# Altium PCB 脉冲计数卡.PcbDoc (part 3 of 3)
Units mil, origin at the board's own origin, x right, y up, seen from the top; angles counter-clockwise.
Board outline 5137.66 x 6771.53 mil, 4 copper layers (Top Layer, GND, VCC, Bottom Layer); 160 components, 225 nets, 1035 pads, 287 vias.
Unrouted connection lines stored in the file: 61.
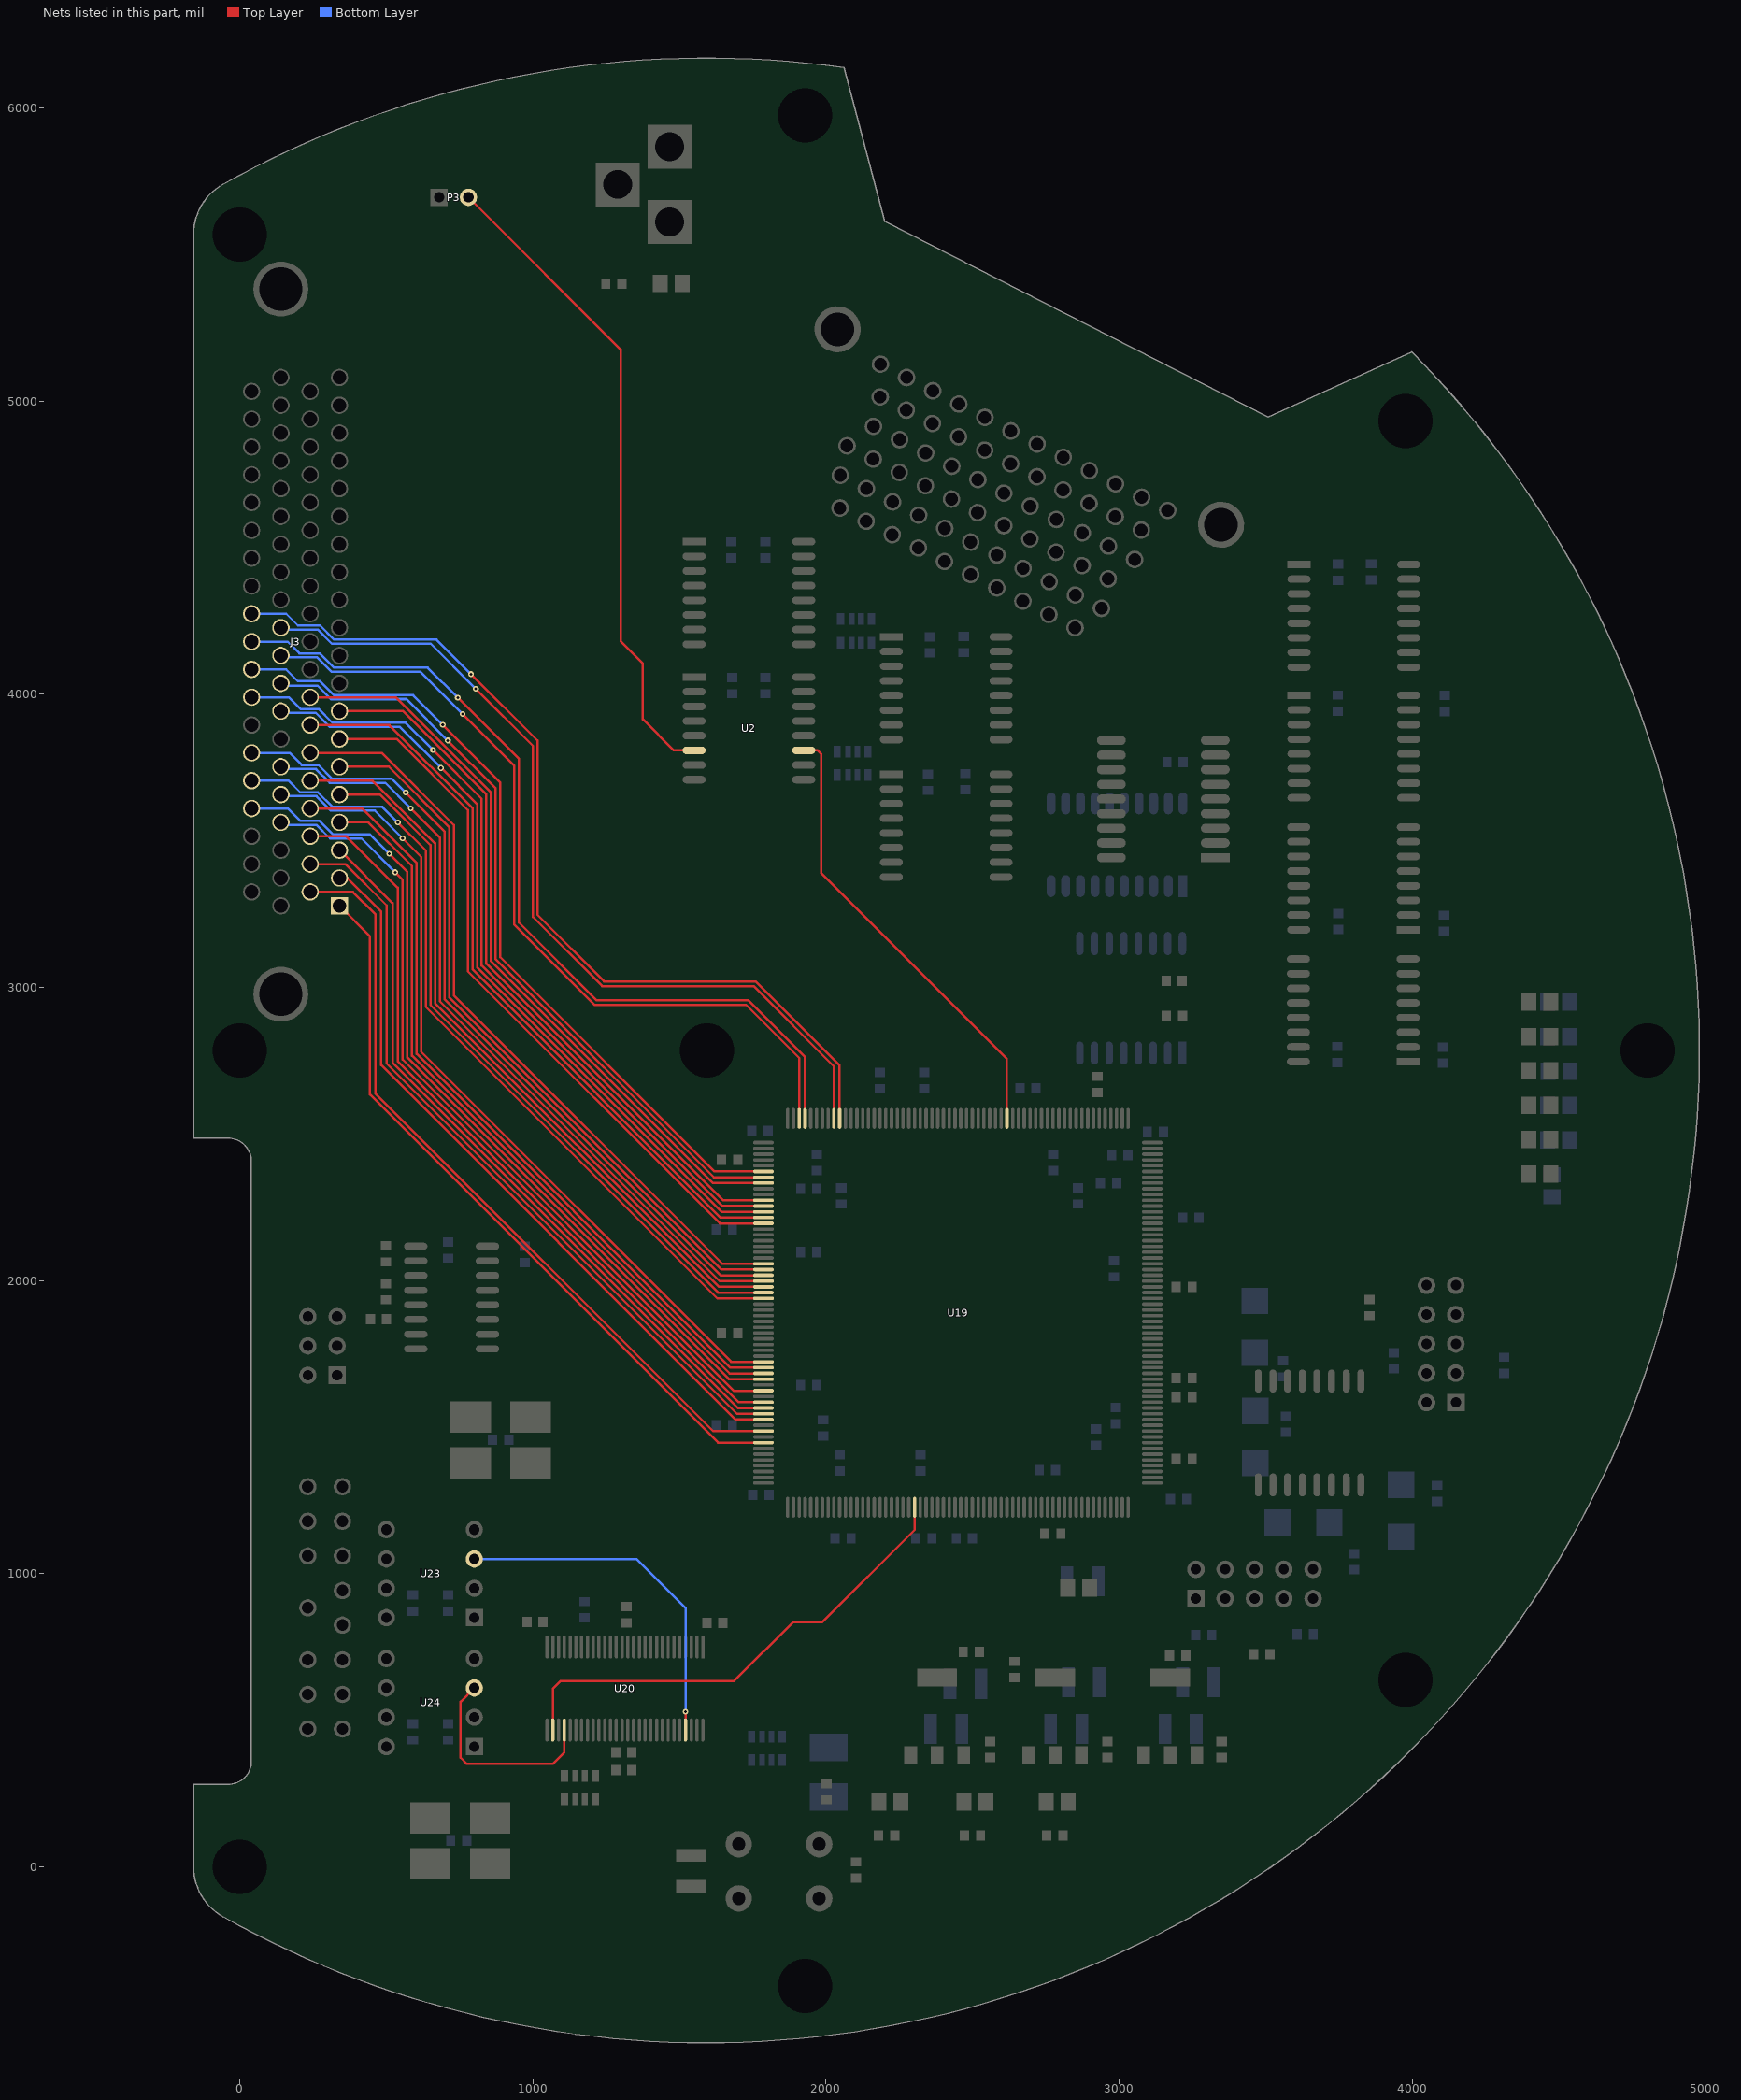
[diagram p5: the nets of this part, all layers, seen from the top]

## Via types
v1: diameter 20, hole 10, Top Layer to Bottom Layer, 184 vias
v2: diameter 40, hole 20, Top Layer to Bottom Layer, 82 vias
v3: diameter 15, hole 8, Top Layer to Bottom Layer, 11 vias
v4: diameter 60, hole 30, Top Layer to Bottom Layer, 8 vias
v5: diameter 30, hole 15, Top Layer to Bottom Layer, 2 vias

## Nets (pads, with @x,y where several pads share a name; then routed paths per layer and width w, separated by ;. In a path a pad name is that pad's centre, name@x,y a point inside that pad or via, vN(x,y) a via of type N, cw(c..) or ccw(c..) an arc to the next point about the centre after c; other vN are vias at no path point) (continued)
TA2: J3.67 U19.144 | length 2820.5
  Top Layer w8: v1(566,3665) 698.32,3532.68 698.32,2959.89 1640.25,2017.95 U19.144@1786.61,2017.95
  Bottom Layer w8: J3.67@40,3800.47 169.53,3800.47 211,3759 268,3759 315,3712 519,3712 v1(566,3665)
TA3: J3.12 U19.142 | length 2609.2
  Top Layer w8: J3.12@240,3800.47 483.91,3800.47 730.06,3554.32 730.06,2973.04 1645.78,2057.32 U19.142@1786.61,2057.32
TA4: J3.13 U19.135 | length 2453.4
  Top Layer w8: J3.13@340,3847.91 535.09,3847.91 777.69,3605.31 777.69,3055.31 1637.88,2195.12 U19.135@1786.61,2195.12
TA5: J3.68 U19.145 | length 2700.5
  Top Layer w8: v1(583,3611) 682.44,3511.56 682.44,2953.31 1637.49,1998.27 U19.145@1786.61,1998.27
  Bottom Layer w8: J3.68@140,3753.03 148.03,3745 260,3745 307,3698 496,3698 v1(583,3611)
TA6: J3.9 U19.147 | length 2469.8
  Top Layer w8: J3.9@340,3658.15 477.85,3658.15 650.69,3485.31 650.69,2940.16 1631.96,1958.9 U19.147@1786.61,1958.9
TA7: J3.11 U19.143 | length 2497.7
  Top Layer w8: J3.11@340,3753.03 508.9,3753.03 714.19,3547.75 714.19,2966.46 1643.01,2037.64 U19.143@1786.61,2037.64
TA8: J3.15 U19.131 | length 2476
  Top Layer w8: J3.15@340,3942.8 557.14,3942.8 841.18,3658.75 841.18,3081.62 1648.94,2273.86 U19.131@1786.61,2273.86
TA9: J3.69 U19.148 | length 2790.8
  Top Layer w8: v1(539,3563) 634.82,3467.18 634.82,2933.59 1629.19,1939.21 U19.148@1786.61,1939.21
  Bottom Layer w8: J3.69@40,3705.59 166.41,3705.59 206,3666 266.38,3666 316.38,3616 486,3616 v1(539,3563)
TA10: J3.72 U19.164 | length 2809.2
  Top Layer w8: v1(530,3393) 555.45,3367.55 555.45,2753.9 1685.1,1624.25 U19.164@1786.61,1624.25
  Bottom Layer w8: J3.72@140,3563.27 148.27,3555 261,3555 308,3508 415,3508 v1(530,3393)
TA11: J3.16 U19.128 | length 2570.2
  Top Layer w8: J3.16@240,3990.24 532.15,3990.24 857.06,3665.33 857.06,3089.94 1614.09,2332.91 U19.128@1786.61,2332.91
TA12: J3.70 U19.159 | length 2837.7
  Top Layer w8: v1(555,3509) 618.95,3445.05 618.95,2780.4 1676.67,1722.68 U19.159@1786.61,1722.68
  Bottom Layer w8: J3.70@140,3658.15 145.15,3653 261,3653 311,3603 461,3603 v1(555,3509)
TA13: J3.71 U19.162 | length 2924.5
  Top Layer w8: v1(510,3456) 571.32,3394.68 571.32,2760.68 1668.38,1663.62 U19.162@1786.61,1663.62
  Bottom Layer w8: J3.71@40,3610.71 164,3610.71 205.71,3569 271,3569 317,3523 443,3523 v1(510,3456)
TA14: J3.14 U19.134 | length 2564.9
  Top Layer w8: J3.14@240,3895.35 510.09,3895.35 793.56,3611.89 793.56,3061.89 1640.65,2214.8 U19.134@1786.61,2214.8
TA15: J3.10 U19.146 | length 2581.3
  Top Layer w8: J3.10@240,3705.59 452.86,3705.59 666.57,3491.88 666.57,2946.74 1634.72,1978.58 U19.146@1786.61,1978.58
TD0: J3.63 U19.132 | length 2798.8
  Top Layer w8: v1(659,3810) 825.31,3643.69 825.31,3075.04 1646.17,2254.17 U19.132@1786.61,2254.17
  Bottom Layer w8: J3.63@40,3990.24 166.76,3990.24 207,3950 269,3950 316,3903 566,3903 v1(659,3810)
TD1: J3.64 U19.133 | length 2680.6
  Top Layer w8: v1(686,3749) 809.43,3625.57 809.43,3068.47 1643.41,2234.49 U19.133@1786.61,2234.49
  Bottom Layer w8: J3.64@140,3942.8 145.8,3937 259,3937 307,3889 546,3889 v1(686,3749)
TD2: J3.6 U19.166 | length 2693.3
  Top Layer w8: J3.6@240,3515.83 363.17,3515.83 539,3340 539,2747.9 1702.02,1584.88 U19.166@1786.61,1584.88
TD3: J3.62 U19.127 | length 2685.8
  Top Layer w8: v1(709.5,3842.5) 872.93,3679.07 872.93,3096.52 1616.85,2352.6 U19.127@1786.61,2352.6
  Bottom Layer w8: J3.62@140,4037.68 147.68,4030 265,4030 311,3984 568,3984 v1(709.5,3842.5)
TD4: J3.7 U19.161 | length 2604.2
  Top Layer w8: J3.7@340,3563.27 438,3563.27 587.2,3414.07 587.2,2767.25 1671.14,1683.31 U19.161@1786.61,1683.31
TD5: J3.5 U19.167 | length 2553.6
  Top Layer w8: J3.5@340,3468.39 521,3287.39 521,2743.45 1699.25,1565.2 U19.167@1786.61,1565.2
TD6: J3.8 U19.160 | length 2718.1
  Top Layer w8: J3.8@240,3610.71 417,3610.71 603.07,3424.64 603.07,2773.83 1673.91,1702.99 U19.160@1786.61,1702.99
TD7: J3.4 U19.168 | length 2639.2
  Top Layer w8: J3.4@240,3420.94 360.06,3420.94 501,3280 501,2741 1696.49,1545.51 U19.168@1786.61,1545.51
TD8: J3.61 U19.126 | length 2805.3
  Top Layer w8: v1(692,3896) 888.8,3699.2 888.8,3103.1 1619.61,2372.28 U19.126@1786.61,2372.28
  Bottom Layer w8: J3.61@40,4085.12 157.88,4085.12 198,4045 274,4045 322,3997 591,3997 v1(692,3896)
TD9: J3.2 U19.171 | length 2668.4
  Top Layer w8: J3.2@240,3326.06 385.94,3326.06 462,3250 462,2639 1614.54,1486.46 U19.171@1786.61,1486.46 U19.171@1784.71,1486.46
TD10: J3.57 U19.111 | length 3173.6
  Top Layer w8: v1(789,4069) 1015.8,3842.2 1015.8,3247.45 1242.88,3020.37 1759.88,3020.37 2046.46,2733.79 U19.111@2046.46,2553.39
  Bottom Layer w8: J3.57@40,4274.88 158.12,4274.88 198,4235 274,4235 322,4187 671,4187 v1(789,4069)
TD11: J3.58 U19.112 | length 3025.9
  Top Layer w8: v1(805,4019) 999.92,3824.08 999.92,3240.88 1236.3,3004.5 1753.3,3004.5 2026.77,2731.03 U19.112@2026.77,2553.39
  Bottom Layer w8: J3.58@140,4227.44 147.44,4220 267,4220 314,4173 651,4173 v1(805,4019)
TD12: J3.3 U19.169 | length 2518.3
  Top Layer w8: J3.3@340,3373.5 366.5,3373.5 482,3258 482,2735 1691.17,1525.83 U19.169@1786.61,1525.83
TD13: J3.60 U19.118 | length 2860.9
  Top Layer w8: v1(760,3933) 936.43,3756.57 936.43,3214.57 1210,2941 1727,2941 1908.66,2759.34 U19.118@1908.66,2553.39
  Bottom Layer w8: J3.60@140,4132.56 146.56,4126 264,4126 312,4078 615,4078 v1(760,3933)
TD14: J3.59 U19.117 | length 3011.6
  Top Layer w8: v1(743.5,3988.5) 952.3,3779.7 952.3,3221.15 1216.58,2956.87 1733.58,2956.87 1928.35,2762.1 U19.117@1928.35,2553.39
  Bottom Layer w8: J3.59@40,4180 163,4180 203,4140 272,4140 321,4091 641,4091 v1(743.5,3988.5)
TD15: J3.1 U19.173 | length 2521.6
  Top Layer w8: J3.1@340,3278.62 444,3174.62 444,2634.55 1631.46,1447.09 U19.173@1786.61,1447.09
TXDA: U20.53 U23.3 | length 1205.8
  Top Layer w8: U20.53@1520.57,466.64 v1(1520.57,529.43)
  Bottom Layer w8: U23.3@800,1050 1353,1050 1520.57,882.43 v1(1520.57,529.43)
TXDB: U20.32 U24.3 | length 712.6
  Top Layer w8: U24.3@800,610 753,563 753,372 774,351 1067.18,351 1107.18,391 U20.32@1107.18,466.64
WRN: U19.203 U20.30 | length 1677
  Top Layer w8: U20.30@1067.81,466.64 1067.81,607.81 1094.13,634.13 1686.58,634.13 1886.58,834.13 1986.58,834.13 2302.36,1149.91 U19.203@2302.36,1226.61
ZHOU: P3.2 U2.6 | length 2246.4
  Top Layer w8: P3.2@780,5696 1298.97,5177.03 1298.97,4181.03 1375,4105 1375,3915 1481,3809 U2.6@1550,3809
ZHOU-A: U2.11 U19.82 | length 1570.3
  Top Layer w8: U2.11@1924.02,3809 1971,3809 1983,3797 1983,3391 2617.32,2756.68 U19.82@2617.32,2553.39
pads on no net: J2.8 J2.9 J2.10 J2.11 J2.12 J2.13 J2.14 J2.15 J2.32 J2.36 J2.39 J2.60 J2.67 J2.68 J3.34 J3.35 J3.39 J3.40 J3.41 J3.42 J3.43 J3.44 J3.45 J3.46 J3.47 J3.48 J3.49 J3.50 J3.51 J3.54 J3.55 J3.56 J3.75 J3.76 J3.77 J3.78 J3.79 J3.80 OSC1.1 OSC2.1 P6.6 P6.7 P6.8 U2.7 U3.7 U4.7 U5.2 U5.3 U5.5 U5.7 U5.9 U5.11 U5.13 U5.15 U5.17 U5.18 U6.6 U6.7 U6.11 U7.7 U8.7 U9.3 U9.4 U9.5 U9.6 U9.11 U9.12 U9.13 U9.14 U12.10 U14.7 U15.7 U16.3 U16.7 U16.14 U19.4 U19.5 U19.6 U19.9 U19.13 U19.18 U19.19 U19.20 U19.21 U19.22 U19.31 U19.32 U19.33 U19.34 U19.80 U19.89 U19.90 U19.91 U19.92 U19.149 U19.151 U19.152 U19.209 U19.210 U19.211 U19.212 U19.235 U19.236 U19.237 U19.238 U19.239 U19.240 U20.14 U20.37 U20.38 U20.39 U20.40 U20.45 U20.46 U20.47 U20.48 U20.56

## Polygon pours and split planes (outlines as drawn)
GND2 on Bottom Layer "Bottom Layer-No Net" (solid, remove dead copper, pour order 1000): 1115,1497 1138,1474 1212,1474 1598,1860 1765,1860 1780,1875 1780,1939 1760,1959 1520,1959 1114,1553 1114,1498
GND2 on GND (split plane): 321 vertices, not listed, extent -137.76,-580.88 4956.49,5557.91
GND1 on GND (split plane): 185 vertices, not listed, extent 70.52,2692.09 4430.45,6150.78
GND2 on GND (split plane): 215.91,5419.09 -137.76,5419.09 -137.76,5569.05 -137.83,5569.75 -137.47,5580.61 -136.34,5592.13 -134.45,5603.55 -131.82,5614.82 -128.47,5625.89 -124.39,5636.72 -119.61,5647.26 -114.16,5657.47 -108.05,5667.3 -101.31,5676.7 -93.96,5685.65 -86.05,5694.1 -77.61,5702.01 -68.66,5709.35 -59.25,5716.09 -49.43,5722.2 -47.71,5723.12 -47.41,5723.25 -47.38,5723.26 -46.71,5723.72 -46.36,5723.92 -45.83,5724.2 -45.77,5724.25 -43.71,5725.42 1.76,5750.29 31.4,5765.91 215.91,5765.91
GND2 on GND (split plane): 4953.56,2992.16 4956.35,2940.4 4958.35,2888.6 4959.55,2836.78 4959.95,2784.95 4959.55,2733.12 4958.35,2681.3 4957.26,2653.09 4665.09,2653.09 4665.09,2998.91 4953.09,2998.91
GND2 on GND (split plane): 4248.55,715.47 4216.37,674.83 4183.56,634.7 4150.14,595.08 4116.12,555.98 4081.49,517.41 4046.28,479.37 4010.49,441.88 3974.12,404.95 3937.18,368.58 3899.7,332.79 3866.09,301.67 3866.09,751.91 4276.52,751.91
GND2 on GND (split plane): 2092.91,-543.62 2059.13,-548.6 2007.74,-555.37 1956.25,-561.34 1904.68,-566.52 1853.03,-570.9 1801.32,-574.49 1749.56,-577.29 1728.09,-578.11 1728.09,-297.09 2092.91,-297.09
GND2 on GND (split plane): 150.91,-255.69 140.41,-250.76 93.84,-228.01 47.62,-204.55 1.76,-180.38 -43.71,-155.51 -45.77,-154.34 -45.83,-154.29 -46.35,-154.02 -46.62,-153.86 -47.24,-153.43 -47.26,-153.42 -47.58,-153.28 -49.43,-152.29 -59.25,-146.18 -68.66,-139.44 -77.61,-132.1 -86.05,-124.19 -93.96,-115.74 -101.31,-106.8 -108.05,-97.39 -114.16,-87.56 -119.61,-77.36 -124.39,-66.82 -128.47,-55.99 -131.82,-44.91 -134.45,-33.64 -136.34,-22.23 -137.47,-10.71 -137.83,0.16 -137.76,0.86 -137.76,137.91 150.91,137.91
GND2 on GND (split plane): 1801.32,6144.4 1853.03,6140.81 1904.67,6136.42 1956.25,6131.24 2007.74,6125.27 2044.9,6120.38 2056.91,6075.39 2056.91,5841.09 1753.09,5841.09 1753.09,6147
GND2 on GND (split plane): 4010.49,5128.02 4046.28,5090.53 4081.49,5052.5 4116.12,5013.92 4150.14,4974.82 4183.56,4935.2 4201.72,4912.99 4017,4728.26 3796.26,4949 3989.25,5141.99 3994.43,5144.33
GND2 on GND (split plane): 148.91,2647.09 -137.76,2647.09 -137.76,2920.91 148.91,2920.91
GND2 on GND (split plane): 1711.91,2642.09 1464.09,2642.09 1464.09,2911.91 1711.91,2911.91
3.3V on VCC (split plane): 263 vertices, not listed, extent -137.76,170.09 4956.6,5557.91
5V on VCC (split plane): 189 vertices, not listed, extent 60.67,2691.09 4430.45,6150.78
5V1 on VCC (split plane): 412.91,160 413.26,157.39 414.27,154.96 415.87,152.87 417.96,151.26 420.39,150.26 423,149.91 2183,149.91 2185.61,150.26 2188.04,151.26 2190.13,152.87 2191.74,154.96 2192.74,157.39 2193.09,160 2193.09,531.91 3843.91,531.91 3843.91,281.64 3823.09,262.95 3783.99,228.93 3744.37,195.51 3704.23,162.7 3663.6,130.52 3622.48,98.96 3580.88,68.05 3538.8,37.77 3496.27,8.15 3453.28,-20.81 3409.85,-49.11 3366,-76.73 3321.72,-103.68 3277.03,-129.94 3231.94,-155.51 3186.47,-180.38 3140.62,-204.55 3094.4,-228.01 3047.82,-250.76 3000.9,-272.79 2953.65,-294.09 2906.07,-314.66 2858.18,-334.49 2809.99,-353.59 2761.52,-371.94 2712.77,-389.54 2663.75,-406.39 2614.48,-422.49 2564.96,-437.82 2515.22,-452.39 2465.26,-466.19 2415.09,-479.22 2364.72,-491.47 2314.18,-502.95 2263.46,-513.65 2212.59,-523.57 2161.56,-532.7 2110.41,-541.04 2110.09,-541.09 2110.09,-288 2109.74,-285.39 2108.74,-282.96 2107.13,-280.87 2105.04,-279.26 2102.61,-278.26 2100,-277.91 1718,-277.91 1715.39,-278.26 1712.96,-279.26 1710.87,-280.87 1709.26,-282.96 1708.26,-285.39 1707.91,-288 1707.91,-578.89 1697.77,-579.28 1645.95,-580.48 1594.12,-580.88 1542.28,-580.48 1490.47,-579.28 1438.67,-577.29 1386.91,-574.49 1335.2,-570.9 1283.56,-566.52 1231.98,-561.34 1180.5,-555.37 1129.11,-548.6 1077.83,-541.04 1026.67,-532.7 975.65,-523.57 924.77,-513.65 874.05,-502.95 823.51,-491.47 773.14,-479.22 722.98,-466.19 673.01,-452.39 623.27,-437.82 573.76,-422.49 524.48,-406.39 475.47,-389.54 426.71,-371.94 378.24,-353.59 330.05,-334.49 282.16,-314.66 234.59,-294.09 187.33,-272.79 170.09,-264.69 170.09,147 169.74,149.61 168.73,152.04 167.13,154.13 165.04,155.74 162.61,156.74 160,157.09 -137.76,157.09 -137.76,260.92 -39.75,260.92 -39.7,260.92 -31.13,261.29 -22.58,262.42 -14.16,264.29 -5.94,266.88 2.02,270.18 9.67,274.16 16.94,278.79 23.78,284.04 30.14,289.87 35.97,296.22 41.22,303.06 45.85,310.34 49.83,317.98 53.13,325.95 55.72,334.17 57.59,342.59 58.71,351.14 59.09,359.7 59.09,359.75 59.09,1401.91 412.91,1401.91
2.5V on VCC (split plane): 2954.91,1211 2955.26,1208.39 2956.26,1205.96 2957.87,1203.87 2959.96,1202.26 2962.39,1201.26 2965,1200.91 3186.91,1200.91 3186.91,552.09 2889.09,552.09 2889.09,1378 2888.74,1380.61 2887.74,1383.04 2886.13,1385.13 2884.04,1386.74 2881.61,1387.74 2879,1388.09 1950.09,1388.09 1950.09,2392.91 2954.91,2392.91
1.2V on VCC (split plane): 3051.91,1221.09 2975.09,1221.09 2975.09,2403 2974.74,2405.61 2973.74,2408.04 2972.13,2410.13 2970.04,2411.74 2967.61,2412.74 2965,2413.09 1940,2413.09 1937.39,2412.74 1934.96,2411.74 1932.87,2410.13 1931.26,2408.04 1930.26,2405.61 1929.91,2403 1929.91,1378 1930.26,1375.39 1931.26,1372.96 1932.87,1370.87 1934.96,1369.26 1937.39,1368.26 1940,1367.91 2868.91,1367.91 2868.91,552.09 2784.09,552.09 2784.09,1277 2783.74,1279.61 2782.74,1282.04 2781.13,1284.13 2779.04,1285.74 2776.61,1286.74 2774,1287.09 1848.09,1287.09 1848.09,2491.91 3051.91,2491.91
FUSE on VCC (split plane): 3130.91,1221.09 3072.09,1221.09 3072.09,2502 3071.74,2504.61 3070.74,2507.04 3069.13,2509.13 3067.04,2510.74 3064.61,2511.74 3062,2512.09 1838,2512.09 1835.39,2511.74 1832.96,2510.74 1830.87,2509.13 1829.26,2507.04 1828.26,2504.61 1827.91,2502 1827.91,1277 1828.26,1274.39 1829.26,1271.96 1830.87,1269.87 1832.96,1268.26 1835.39,1267.26 1838,1266.91 2763.91,1266.91 2763.91,1239.09 1785.09,1239.09 1785.09,2544.91 3130.91,2544.91
3.3V on VCC (split plane): 220.91,5416.09 -137.76,5416.09 -137.76,5569.05 -137.83,5569.75 -137.47,5580.61 -136.34,5592.13 -134.45,5603.55 -131.82,5614.82 -128.47,5625.89 -124.39,5636.72 -119.61,5647.26 -114.16,5657.47 -108.05,5667.3 -101.31,5676.7 -93.96,5685.65 -86.05,5694.1 -77.61,5702.01 -68.66,5709.35 -59.25,5716.09 -49.43,5722.2 -47.71,5723.12 -47.41,5723.25 -47.38,5723.26 -46.71,5723.72 -46.36,5723.92 -45.83,5724.2 -45.77,5724.25 -43.71,5725.42 1.76,5750.29 21.92,5760.91 220.91,5760.91
3.3V on VCC (split plane): 4953.56,2992.16 4956.35,2940.4 4958.35,2888.6 4959.55,2836.78 4959.95,2784.95 4959.55,2733.12 4958.35,2681.3 4957.38,2656.09 4666.09,2656.09 4666.09,3001.91 4952.88,3001.91
3.3V on VCC (split plane): 4248.55,715.47 4216.37,674.83 4183.56,634.7 4150.14,595.08 4116.12,555.98 4081.49,517.41 4046.28,479.37 4010.49,441.88 3974.12,404.95 3937.18,368.58 3899.7,332.79 3864.09,299.82 3864.09,707.82 3910.18,753.91 4278.05,753.91
3.3V on VCC (split plane): 2089.91,-544.06 2059.13,-548.6 2007.74,-555.37 1956.25,-561.34 1904.68,-566.52 1853.03,-570.9 1801.32,-574.49 1749.56,-577.29 1728.09,-578.11 1728.09,-298.09 2089.91,-298.09
3.3V on VCC (split plane): 149.91,-255.22 140.41,-250.76 93.84,-228.01 47.62,-204.55 1.76,-180.38 -43.71,-155.51 -45.77,-154.34 -45.83,-154.29 -46.35,-154.02 -46.62,-153.86 -47.24,-153.43 -47.26,-153.42 -47.58,-153.28 -49.43,-152.29 -59.25,-146.18 -68.66,-139.44 -77.61,-132.1 -86.05,-124.19 -93.96,-115.74 -101.31,-106.8 -108.05,-97.39 -114.16,-87.56 -119.61,-77.36 -124.39,-66.82 -128.47,-55.99 -131.82,-44.91 -134.45,-33.64 -136.34,-22.23 -137.47,-10.71 -137.83,0.16 -137.76,0.86 -137.76,136.91 149.91,136.91
3.3V on VCC (split plane): 1801.32,6144.4 1853.03,6140.81 1904.67,6136.42 1956.25,6131.24 2007.74,6125.27 2044.9,6120.38 2054.91,6082.88 2054.91,5838.09 1753.09,5838.09 1753.09,6147
3.3V on VCC (split plane): 4010.49,5128.02 4046.28,5090.53 4081.49,5052.5 4116.12,5013.92 4150.14,4974.82 4183.56,4935.2 4203.52,4910.79 4016,4723.26 3921.54,4817.73 3792.26,4947 3985.6,5140.34 3994.43,5144.33
3.3V on VCC (split plane): 148.91,2645.09 -137.76,2645.09 -137.76,2920.91 148.91,2920.91
3.3V on VCC (split plane): 1711.91,2645.09 1468.09,2645.09 1468.09,2909.91 1711.91,2909.91

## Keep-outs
Keep-Out Layer:
  circle w5: c0.3,0.12 r90.55
  circle w5: c-0.38,2784.95 r90.55
  circle w5: c-0.38,5569.39 r90.55
  circle w5: c1929.51,5976.04 r90.55
  circle w5: c3978.62,4931.97 r90.55
  circle w5: c4802.78,2784.95 r90.55
  circle w5: c3978.62,637.94 r90.55
  circle w5: c1929.51,-406.13 r90.55
  lines w5: -57.03,5740.89 cw(c1594.11,2784.95) 2061.06,6138.43 ; -57,5740.91 ccw(c38.99,5569.05) -157.86,5569.05 -157.86,2784.95 -157.86,2485.74 -39.75,2485.74 cw(c-39.75,2407) 38.99,2407 38.99,359.75 cw(c-39.75,359.75) -39.75,281.01 -157.86,281.01 -157.86,0.86 ccw(c38.99,0.86) -57,-171 ccw(c1594.12,2784.95) 3998.64,5168.67 ; 2061,6138 2201.09,5613.19 ; 2205.35,5610.72 3508.63,4946.67 ; 3508.67,4946.74 3998,5168

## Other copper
GND (plane layer: these items are gaps in the copper):
  lines w20: -160,2641 -164,2637 159,2637 159,2931 -157.86,2931 ; -157.86,148 161,148 161,-280 ; -150.86,5409 226,5409 226,5776 3,5776 ; 226,5568 770,5568 1268,5070 1268,3903 1521,3650 1685,3650 1685,4578 1998,4578 1998,3512 2182,3328 2367,3328 2367,4244 2683,4244 2683,3206 2916,2973 3295,2973 3586,2682 3776,2682 3776,4587 4450,4587 ; 1454,2919 1454,2632 1701,2632 1722,2632 1722,2922 1457,2922 ; 1718,-600 1718,-295 1718,-287 2103,-287 2103,-562 ; 1743,6168 1743,5831 2067,5831 2067,6139 ; 3856,266 3856,762 4311,762 ; 4002,5164 3997,5164 3782,4949 4017,4714 4217,4914 ; 4956,2379 4957,2380 ; 4969,3009 4655,3009 4655,2643 4971,2643
VCC (plane layer: these items are gaps in the copper):
  lines w20: -157.86,147 160,147 160,-285 ; -157.86,2635 157,2635 159,2637 159,2927 ; -157.86,2931 155,2931 ; -151.86,5406 231,5406 231,5771 -11,5771 ; 37,1412 423,1412 423,160 2183,160 2183,542 2780,542 ; 231,5568 767,5568 1270,5065 1270,3906 1525,3651 1686,3651 1686,4578 1998,4578 1998,3512 2181,3329 2364,3329 2366,3331 2366,3512 2366,4243 2685,4243 2685,3202 2913,2974 3291,2974 3584,2681 3776,2681 3776,4587 4454,4587 ; 1458,2919 1458,2636 1459,2635 1722,2635 1722,2920 1459,2920 ; 1718,-598 1718,-288 2100,-288 2100,-568 ; 1743,6171 1743,5829 1744,5828 2065,5828 2065,6145 ; 2768,1229 1775,1229 1775,2555 3141,2555 3141,1211 ; 2868,542 3197,542 ; 3853,542 3197,542 ; 3854,267 3854,712 ; 3854,702 3854,712 ; 3914.41,4810.59 4016.36,4708.64 4016.36,4708.36 ; 3946,4779 3778,4947 3995,5164 3995,5169 ; 4016,4709 4223,4916 4231,4916 ; 4314,764 3906,764 3854,712 ; 4977,2646 4656,2646 4656,3012 4978,3012 ; 3062,1211 3197,1211 3197,542 ; 3062,1211 2965,1211 2965,2403 1940,2403 1940,1378 2879,1378 2879,542 2774,542 2774,1277 1838,1277 1838,2502 3062,2502 3062,1211

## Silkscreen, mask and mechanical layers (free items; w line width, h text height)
Top Overlay:
  text "5V" at 1423,5269 h60
Mechanical 2:
  circle w5: c1594.11,2784.95 r90.55
  lines w5: 2201.09,5613.19 2205.35,5610.72
Mechanical 3:
  circle w5: c3978.62,4931.97 r90.55
  circle w5: c1929.51,5976.04 r90.55
  circle w5: c3978.62,637.94 r90.55
  circle w5: c4802.78,2784.95 r90.55
  circle w5: c1929.51,-406.13 r90.55
  circle w5: c-0.38,5569.39 r90.55
  circle w5: c-0.38,2784.95 r90.55
  circle w5: c0.3,0.12 r90.55
  circle w5: c1594.54,2785.01 r90.55
  lines w5: 2125.09,6128.89 ccw(c1594.11,2784.95) -57,5740.91 ccw(c38.99,5569.05) -157.86,5569.05 -157.86,2784.95 -157.86,2485.74 -39.75,2485.74 cw(c-39.75,2407) 38.99,2407 38.99,359.75 cw(c-39.75,359.75) -39.75,281.01 -157.86,281.01 -157.86,0.86 ccw(c38.99,0.86) -57,-171 ccw(c1594.12,2784.95) 3987.31,5180.04 ccw(c3848.17,5040.79) 3672.78,5130.16 3600.47,4988.25 cw(c3530.31,5023.99) 3494.57,4953.84 2231.72,5597.29 cw(c2267.47,5667.45) 2197.31,5703.19 2269.62,5845.1
Mechanical 4:
  circle w5: c3978.62,4931.97 r90.55
  circle w5: c1929.51,5976.04 r90.55
  circle w5: c3978.62,637.94 r90.55
  circle w5: c4802.78,2784.95 r90.55
  circle w5: c1929.51,-406.13 r90.55
  circle w5: c-0.38,5569.39 r90.55
  circle w5: c-0.38,2784.95 r90.55
  circle w5: c0.3,0.12 r90.55
  circle w5: c1594.11,2784.95 r90.55
  circle w5: c1594.11,2784.95 r3208.66
  lines w5: 2125.09,6128.89 ccw(c1594.11,2784.95) -57,5740.91 ccw(c38.99,5569.05) -157.86,5569.05 -157.86,2784.95 -157.86,2485.74 -39.75,2485.74 cw(c-39.75,2407) 38.99,2407 38.99,359.75 cw(c-39.75,359.75) -39.75,281.01 -157.86,281.01 -157.86,0.86 ccw(c38.99,0.86) -57,-171 ccw(c1594.12,2784.95) 3987.31,5180.04 ccw(c3848.17,5040.79) 3672.78,5130.16 3600.47,4988.25 cw(c3530.31,5023.99) 3494.57,4953.84 2231.72,5597.29 cw(c2267.47,5667.45) 2197.31,5703.19 2269.62,5845.1
Mechanical 5:
  circle w5: c3978.62,4931.97 r90.55
  circle w5: c1929.51,5976.04 r90.55
  circle w5: c3978.62,637.94 r90.55
  circle w5: c4802.78,2784.95 r90.55
  circle w5: c1929.51,-406.13 r90.55
  circle w5: c-0.38,5569.39 r90.55
  circle w5: c-0.38,2784.95 r90.55
  circle w5: c0.3,0.12 r90.55
  circle w5: c1594.11,2784.95 r90.55
  circle w5: c1594.11,2784.95 r3208.66
  lines w5: 2125.09,6128.89 ccw(c1594.11,2784.95) -57,5740.91 ccw(c38.99,5569.05) -157.86,5569.05 -157.86,2784.95 -157.86,2485.74 -39.75,2485.74 cw(c-39.75,2407) 38.99,2407 38.99,359.75 cw(c-39.75,359.75) -39.75,281.01 -157.86,281.01 -157.86,0.86 ccw(c38.99,0.86) -57,-171 ccw(c1594.12,2784.95) 3987.31,5180.04 ccw(c3848.17,5040.79) 3672.78,5130.16 3600.47,4988.25 cw(c3530.31,5023.99) 3494.57,4953.84 2231.72,5597.29 cw(c2267.47,5667.45) 2197.31,5703.19 2269.62,5845.1
Mechanical 6:
  circle w5: c3978.62,4931.97 r90.55
  circle w5: c1929.51,5976.04 r90.55
  circle w5: c3978.62,637.94 r90.55
  circle w5: c4802.78,2784.95 r90.55
  circle w5: c1929.51,-406.13 r90.55
  circle w5: c-0.38,5569.39 r90.55
  circle w5: c-0.38,2784.95 r90.55
  circle w5: c0.3,0.12 r90.55
  circle w5: c1594.11,2784.95 r90.55
  circle w5: c1594.11,2784.95 r3208.66
  lines w5: 2125.09,6128.89 ccw(c1594.11,2784.95) -57,5740.91 ccw(c38.99,5569.05) -157.86,5569.05 -157.86,2784.95 -157.86,2485.74 -39.75,2485.74 cw(c-39.75,2407) 38.99,2407 38.99,359.75 cw(c-39.75,359.75) -39.75,281.01 -157.86,281.01 -157.86,0.86 ccw(c38.99,0.86) -57,-171 ccw(c1594.12,2784.95) 3987.31,5180.04 ccw(c3848.17,5040.79) 3672.78,5130.16 3600.47,4988.25 cw(c3530.31,5023.99) 3494.57,4953.84 2231.72,5597.29 cw(c2267.47,5667.45) 2197.31,5703.19 2269.62,5845.1
Mechanical 7:
  circle w5: c1929.51,5976.04 r90.55
  circle w5: c3978.62,4931.97 r90.55
  circle w5: c0.3,0.12 r90.55
  circle w5: c1929.51,-406.13 r90.55
  circle w5: c3978.62,637.94 r90.55
  circle w5: c-0.38,2784.95 r90.55
  circle w5: c-0.38,5569.39 r90.55
  circle w5: c1594.11,2784.95 r90.55
  circle w5: c4802.78,2784.95 r90.55
  circle w5: c1594.11,2784.95 r3208.66
  lines w5: 2125.09,6128.89 ccw(c1594.11,2784.95) -57,5740.91 ccw(c38.99,5569.05) -157.86,5569.05 -157.86,2784.95 -157.86,2485.74 -39.75,2485.74 cw(c-39.75,2407) 38.99,2407 38.99,359.75 cw(c-39.75,359.75) -39.75,281.01 -157.86,281.01 -157.86,0.86 ccw(c38.99,0.86) -57,-171 ccw(c1594.12,2784.95) 3987.31,5180.04 ccw(c3848.17,5040.79) 3672.78,5130.16 3600.47,4988.25 cw(c3530.31,5023.99) 3494.57,4953.84 2231.72,5597.29 cw(c2267.47,5667.45) 2197.31,5703.19 2269.62,5845.1
Mechanical 8:
  circle w5: c3978.62,4931.97 r90.55
  circle w5: c1929.51,5976.04 r90.55
  circle w5: c3978.62,637.94 r90.55
  circle w5: c4802.78,2784.95 r90.55
  circle w5: c1929.51,-406.13 r90.55
  circle w5: c-0.38,5569.39 r90.55
  circle w5: c-0.38,2784.95 r90.55
  circle w5: c0.3,0.12 r90.55
  circle w5: c1594.11,2784.95 r90.55
  circle w5: c1594.11,2784.95 r3208.66
  lines w5: 2125.09,6128.89 ccw(c1594.11,2784.95) -57,5740.91 ccw(c38.99,5569.05) -157.86,5569.05 -157.86,2784.95 -157.86,2485.74 -39.75,2485.74 cw(c-39.75,2407) 38.99,2407 38.99,359.75 cw(c-39.75,359.75) -39.75,281.01 -157.86,281.01 -157.86,0.86 ccw(c38.99,0.86) -57,-171 ccw(c1594.12,2784.95) 3987.31,5180.04 ccw(c3848.17,5040.79) 3672.78,5130.16 3600.47,4988.25 cw(c3530.31,5023.99) 3494.57,4953.84 2231.72,5597.29 cw(c2267.47,5667.45) 2197.31,5703.19 2269.62,5845.1
Mechanical 9:
  circle w5: c3978.62,4931.97 r90.55
  circle w5: c1929.51,5976.04 r90.55
  circle w5: c3978.62,637.94 r90.55
  circle w5: c4802.78,2784.95 r90.55
  circle w5: c1929.51,-406.13 r90.55
  circle w5: c-0.38,5569.39 r90.55
  circle w5: c-0.38,2784.95 r90.55
  circle w5: c0.3,0.12 r90.55
  circle w5: c1594.11,2784.95 r90.55
  circle w5: c1594.11,2784.95 r3208.66
  lines w5: 2125.09,6128.89 ccw(c1594.11,2784.95) -57,5740.91 ccw(c38.99,5569.05) -157.86,5569.05 -157.86,2784.95 -157.86,2485.74 -39.75,2485.74 cw(c-39.75,2407) 38.99,2407 38.99,359.75 cw(c-39.75,359.75) -39.75,281.01 -157.86,281.01 -157.86,0.86 ccw(c38.99,0.86) -57,-171 ccw(c1594.12,2784.95) 3987.31,5180.04 ccw(c3848.17,5040.79) 3672.78,5130.16 3600.47,4988.25 cw(c3530.31,5023.99) 3494.57,4953.84 2231.72,5597.29 cw(c2267.47,5667.45) 2197.31,5703.19 2269.62,5845.1
Mechanical 10:
  circle w5: c3978.62,4931.97 r90.55
  circle w5: c1929.51,5976.04 r90.55
  circle w5: c3978.62,637.94 r90.55
  circle w5: c4802.78,2784.95 r90.55
  circle w5: c1929.51,-406.13 r90.55
  circle w5: c-0.38,5569.39 r90.55
  circle w5: c-0.38,2784.95 r90.55
  circle w5: c0.3,0.12 r90.55
  circle w5: c1594.11,2784.95 r90.55
  circle w5: c1594.11,2784.95 r3208.66
  lines w5: 2125.09,6128.89 ccw(c1594.11,2784.95) -57,5740.91 ccw(c38.99,5569.05) -157.86,5569.05 -157.86,2784.95 -157.86,2485.74 -39.75,2485.74 cw(c-39.75,2407) 38.99,2407 38.99,359.75 cw(c-39.75,359.75) -39.75,281.01 -157.86,281.01 -157.86,0.86 ccw(c38.99,0.86) -57,-171 ccw(c1594.12,2784.95) 3987.31,5180.04 ccw(c3848.17,5040.79) 3672.78,5130.16 3600.47,4988.25 cw(c3530.31,5023.99) 3494.57,4953.84 2231.72,5597.29 cw(c2267.47,5667.45) 2197.31,5703.19 2269.62,5845.1
Mechanical 11:
  circle w5: c3978.62,4931.97 r90.55
  circle w5: c1929.51,5976.04 r90.55
  circle w5: c3978.62,637.94 r90.55
  circle w5: c4802.78,2784.95 r90.55
  circle w5: c1929.51,-406.13 r90.55
  circle w5: c-0.38,5569.39 r90.55
  circle w5: c-0.38,2784.95 r90.55
  circle w5: c0.3,0.12 r90.55
  circle w5: c1594.11,2784.95 r90.55
  circle w5: c1594.11,2784.95 r3208.66
  lines w5: -157.86,0.86 ccw(c38.99,0.86) -57,-171 ccw(c1594.12,2784.95) 3987.31,5180.04 ccw(c3848.17,5040.79) 3672.78,5130.16 3600.47,4988.25 cw(c3530.31,5023.99) 3494.57,4953.84 2231.72,5597.29 cw(c2267.47,5667.45) 2197.31,5703.19 2269.62,5845.1 ccw(c2094.22,5934.47) 2125.09,6128.89 ccw(c1594.11,2784.95) -57,5740.91 ccw(c38.99,5569.05) -157.86,5569.05 -157.86,2784.95 -157.86,2485.74 -39.75,2485.74 cw(c-39.75,2407) 38.99,2407 38.99,359.75 cw(c-39.75,359.75) -39.75,281.01 -157.86,281.01 -157.86,0.86
Mechanical 12:
  circle w5: c3978.62,4931.97 r90.55
  circle w5: c1929.51,5976.04 r90.55
  circle w5: c3978.62,637.94 r90.55
  circle w5: c4802.78,2784.95 r90.55
  circle w5: c1929.51,-406.13 r90.55
  circle w5: c-0.38,5569.39 r90.55
  circle w5: c-0.38,2784.95 r90.55
  circle w5: c0.3,0.12 r90.55
  circle w5: c1594.11,2784.95 r90.55
  circle w5: c1594.11,2784.95 r3208.66
  lines w5: -157.86,0.86 ccw(c38.99,0.86) -57,-171 ccw(c1594.12,2784.95) 3987.31,5180.04 ccw(c3848.17,5040.79) 3672.78,5130.16 3600.47,4988.25 cw(c3530.31,5023.99) 3494.57,4953.84 2231.72,5597.29 cw(c2267.47,5667.45) 2197.31,5703.19 2269.62,5845.1 ccw(c2094.22,5934.47) 2125.09,6128.89 ccw(c1594.11,2784.95) -57,5740.91 ccw(c38.99,5569.05) -157.86,5569.05 -157.86,2784.95 -157.86,2485.74 -39.75,2485.74 cw(c-39.75,2407) 38.99,2407 38.99,359.75 cw(c-39.75,359.75) -39.75,281.01 -157.86,281.01 -157.86,0.86
Mechanical 13:
  circle w5: c3978.62,4931.97 r90.55
  circle w5: c1929.51,5976.04 r90.55
  circle w5: c3978.62,637.94 r90.55
  circle w5: c4802.78,2784.95 r90.55
  circle w5: c1929.51,-406.13 r90.55
  circle w5: c-0.38,5569.39 r90.55
  circle w5: c-0.38,2784.95 r90.55
  circle w5: c0.3,0.12 r90.55
  circle w5: c1594.11,2784.95 r90.55
  circle w5: c1594.11,2784.95 r3208.66
  lines w5: -157.86,0.86 ccw(c38.99,0.86) -57,-171 ccw(c1594.12,2784.95) 3987.31,5180.04 ccw(c3848.17,5040.79) 3672.78,5130.16 3600.47,4988.25 cw(c3530.31,5023.99) 3494.57,4953.84 2231.72,5597.29 cw(c2267.47,5667.45) 2197.31,5703.19 2269.62,5845.1 ccw(c2094.22,5934.47) 2125.09,6128.89 ccw(c1594.11,2784.95) -57,5740.91 ccw(c38.99,5569.05) -157.86,5569.05 -157.86,2784.95 -157.86,2485.74 -39.75,2485.74 cw(c-39.75,2407) 38.99,2407 38.99,359.75 cw(c-39.75,359.75) -39.75,281.01 -157.86,281.01 -157.86,0.86
Mechanical 14:
  circle w5: c3978.62,4931.97 r90.55
  circle w5: c1929.51,5976.04 r90.55
  circle w5: c3978.62,637.94 r90.55
  circle w5: c4802.78,2784.95 r90.55
  circle w5: c1929.51,-406.13 r90.55
  circle w5: c-0.38,5569.39 r90.55
  circle w5: c-0.38,2784.95 r90.55
  circle w5: c0.3,0.12 r90.55
  circle w5: c1594.11,2784.95 r90.55
  circle w5: c1594.11,2784.95 r3208.66
  lines w5: -157.86,0.86 ccw(c38.99,0.86) -57,-171 ccw(c1594.12,2784.95) 3987.31,5180.04 ccw(c3848.17,5040.79) 3672.78,5130.16 3600.47,4988.25 cw(c3530.31,5023.99) 3494.57,4953.84 2231.72,5597.29 cw(c2267.47,5667.45) 2197.31,5703.19 2269.62,5845.1 ccw(c2094.22,5934.47) 2125.09,6128.89 ccw(c1594.11,2784.95) -57,5740.91 ccw(c38.99,5569.05) -157.86,5569.05 -157.86,2784.95 -157.86,2485.74 -39.75,2485.74 cw(c-39.75,2407) 38.99,2407 38.99,359.75 cw(c-39.75,359.75) -39.75,281.01 -157.86,281.01 -157.86,0.86
Mechanical 15:
  circle w5: c3978.62,4931.97 r90.55
  circle w5: c1929.51,5976.04 r90.55
  circle w5: c3978.62,637.94 r90.55
  circle w5: c4802.78,2784.95 r90.55
  circle w5: c1929.51,-406.13 r90.55
  circle w5: c-0.38,5569.39 r90.55
  circle w5: c-0.38,2784.95 r90.55
  circle w5: c0.3,0.12 r90.55
  circle w5: c1594.11,2784.95 r90.55
  circle w5: c1594.11,2784.95 r3208.66
  lines w5: -157.86,0.86 ccw(c38.99,0.86) -57,-171 ccw(c1594.12,2784.95) 3987.31,5180.04 ccw(c3848.17,5040.79) 3672.78,5130.16 3600.47,4988.25 cw(c3530.31,5023.99) 3494.57,4953.84 2231.72,5597.29 cw(c2267.47,5667.45) 2197.31,5703.19 2269.62,5845.1 ccw(c2094.22,5934.47) 2125.09,6128.89 ccw(c1594.11,2784.95) -57,5740.91 ccw(c38.99,5569.05) -157.86,5569.05 -157.86,2784.95 -157.86,2485.74 -39.75,2485.74 cw(c-39.75,2407) 38.99,2407 38.99,359.75 cw(c-39.75,359.75) -39.75,281.01 -157.86,281.01 -157.86,0.86
Mechanical 16:
  circle w5: c3978.62,4931.97 r90.55
  circle w5: c1929.51,5976.04 r90.55
  circle w5: c3978.62,637.94 r90.55
  circle w5: c4802.78,2784.95 r90.55
  circle w5: c1929.51,-406.13 r90.55
  circle w5: c-0.38,5569.39 r90.55
  circle w5: c-0.38,2784.95 r90.55
  circle w5: c0.3,0.12 r90.55
  circle w5: c1594.11,2784.95 r90.55
  circle w5: c1594.11,2784.95 r3208.66
  lines w5: -157.86,0.86 ccw(c38.99,0.86) -57,-171 ccw(c1594.12,2784.95) 3987.31,5180.04 ccw(c3848.17,5040.79) 3672.78,5130.16 3600.47,4988.25 cw(c3530.31,5023.99) 3494.57,4953.84 2231.72,5597.29 cw(c2267.47,5667.45) 2197.31,5703.19 2269.62,5845.1 ccw(c2094.22,5934.47) 2125.09,6128.89 ccw(c1594.11,2784.95) -57,5740.91 ccw(c38.99,5569.05) -157.86,5569.05 -157.86,2784.95 -157.86,2485.74 -39.75,2485.74 cw(c-39.75,2407) 38.99,2407 38.99,359.75 cw(c-39.75,359.75) -39.75,281.01 -157.86,281.01 -157.86,0.86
